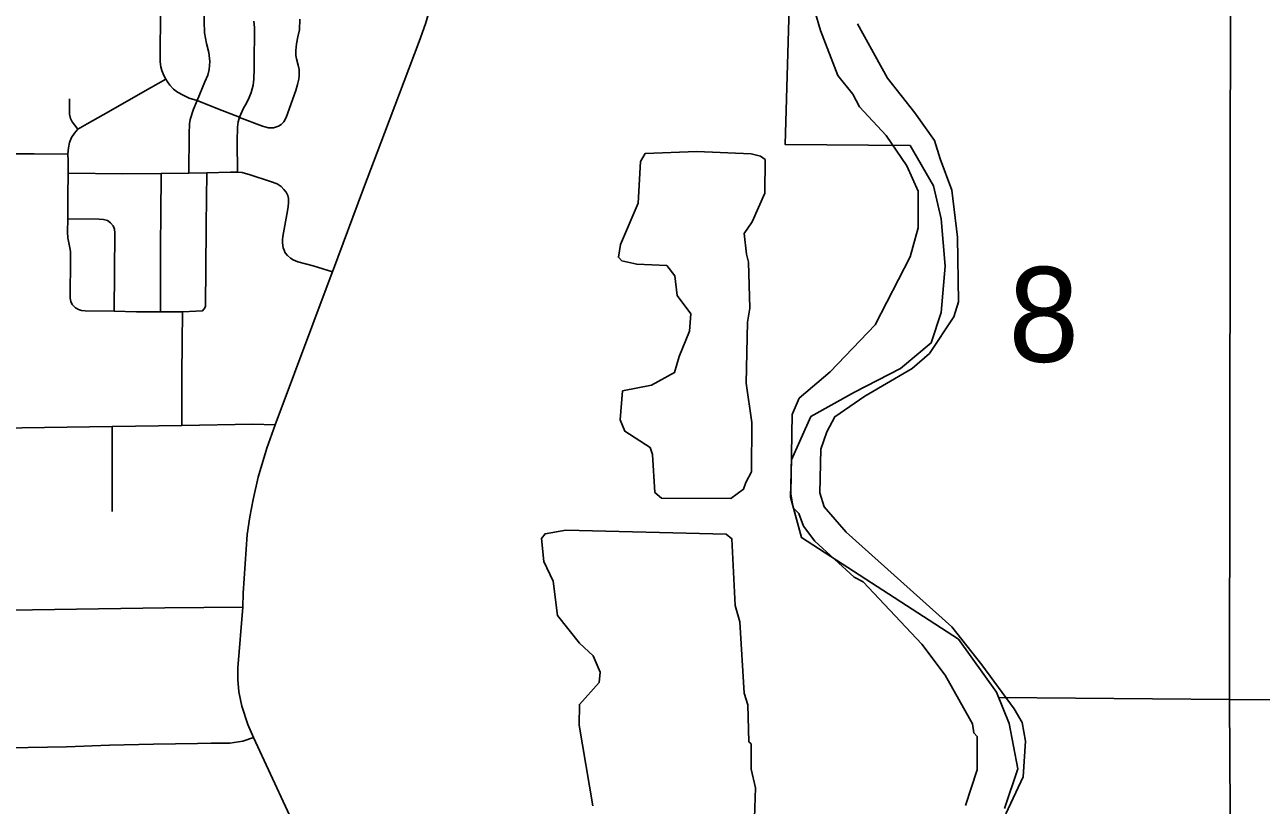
# Model space of a CAD drawing. Extents: x -1403959 to 81668, y -1400582 to 11018.
# Drawn here: x 6835.6 to 6999.4, y 8704.7 to 8808.1 of the extents above; entities that cross this region are included whole.
import ezdxf

# ---------------------------------------------------------------- set-up
doc = ezdxf.new("R2010")
doc.units = 0
for name, color, linetype in [('tdCiRRCL', 7, 'Continuous'), ('tdCiSectNmbr', 7, 'Continuous'), ('tdCiSectTwpRng', 7, 'Continuous'), ('tdCoCityStreetMajor', 7, 'Continuous'), ('tdCoSectLinePart', 7, 'Continuous'), ('tdCoSurfBitum', 7, 'Continuous')]:
    doc.layers.add(name, color=color, linetype=linetype)

msp = doc.modelspace()

# ---------------------------------------------------------------- linework, layer by layer
at = {"layer": 'tdCiRRCL'}
msp.add_lwpolyline([(6936.92, 8811.88), (6936.35, 8792.18), (6952.9, 8792.06), (6956.01, 8786.73), (6956.99, 8782.37), (6957.52, 8776.1), (6957.02, 8769.93), (6955.67, 8765.92), (6951.62, 8762.52), (6945.52, 8759.39), (6939.77, 8756.17), (6937.17, 8750.45), (6937.04, 8745.49), (6938.51, 8740.14), (6959.32, 8726.66), (6964.34, 8719.67), (6966.03, 8715.52), (6967.15, 8709.51), (6965.39, 8704.23)], dxfattribs=at)
at = {"layer": 'tdCiSectNmbr'}
for points in [[(6883.27, 8793.7), (6887.87, 8805.86), (6888.7, 8808.19), (6889.16, 8809.67), (6889.53, 8811.27), (6889.79, 8813.54), (6889.88, 8816.53)], [(6876.35, 8775.24), (6876.39, 8775.35), (6880.5, 8786.37), (6883.27, 8793.7)], [(6864.52, 8730.9), (6864.52, 8730.91), (6864.58, 8732.76), (6865.12, 8740.53), (6865.48, 8742.89), (6865.88, 8745.2), (6866.55, 8748.12), (6867.72, 8751.98), (6868.82, 8755.05), (6876.35, 8775.24)], [(6863.87, 8722.89), (6864.52, 8730.9)], [(6865.96, 8713.64), (6865.2, 8715.36), (6864.42, 8717.8), (6864, 8719.71), (6863.87, 8721.33), (6863.87, 8722.89)], [(6877.05, 8689.29), (6876.08, 8691.57), (6874.93, 8694.25), (6865.96, 8713.64)]]:
    msp.add_lwpolyline(points, dxfattribs=at)
at = {"layer": 'tdCiSectTwpRng'}
for points in [[(6864.08, 8795.81), (6861.23, 8796.91), (6858.48, 8798.01), (6857.44, 8798.35), (6856.61, 8798.73), (6855.88, 8799.15), (6855.34, 8799.55), (6854.87, 8800.06), (6854.56, 8800.5), (6854.32, 8800.85), (6854.08, 8801.32), (6853.81, 8801.99), (6853.67, 8802.5), (6853.6, 8803.14), (6853.58, 8803.62), (6853.57, 8804.36), (6853.6, 8805.45), (6853.67, 8810.75), (6853.71, 8815.6)], [(6857.39, 8788.4), (6857.42, 8793.6), (6857.45, 8794.93), (6857.57, 8795.52), (6858.02, 8796.87), (6858.48, 8798.01), (6859.52, 8800.52), (6859.9, 8801.4), (6860.06, 8802.13), (6860.14, 8803.19), (6860.03, 8804.38), (6859.72, 8805.58), (6859.46, 8807), (6859.41, 8808.5), (6859.44, 8809.93), (6859.59, 8810.86), (6859.86, 8811.38), (6860.25, 8811.69), (6860.84, 8811.9), (6861.75, 8811.95), (6862.5, 8812.06), (6864.18, 8812.79)], [(6863.82, 8788.54), (6863.77, 8792.65), (6863.81, 8794.49), (6863.93, 8795.21), (6864.08, 8795.81), (6864.64, 8797), (6865.03, 8797.67), (6865.39, 8798.41), (6865.64, 8799.09), (6865.88, 8800.06), (6866, 8800.87), (6866.05, 8802.22), (6866.05, 8803.65), (6866.09, 8806.82), (6866.07, 8807.7), (6865.98, 8808.55)], [(6864.11, 8795.79), (6867.13, 8794.65), (6867.44, 8794.54), (6867.92, 8794.41), (6868.23, 8794.41), (6868.59, 8794.4), (6868.87, 8794.49), (6869.24, 8794.62), (6869.61, 8794.84), (6869.96, 8795.21), (6870.26, 8795.77), (6871.55, 8799.35), (6871.79, 8800.13), (6871.95, 8800.84), (6872, 8801.3), (6872.01, 8801.73), (6871.99, 8802.13), (6871.86, 8802.72), (6871.66, 8803.56), (6871.57, 8803.98), (6871.53, 8804.65), (6871.62, 8805.54), (6871.83, 8806.46), (6872.05, 8807.38), (6872.1, 8808.81)], [(6842.68, 8794.25), (6843.92, 8794.93), (6846.76, 8796.51), (6851.27, 8799.12), (6854.32, 8800.85)], [(6842.39, 8770.55), (6842.14, 8770.79), (6841.94, 8771.02), (6841.75, 8771.39), (6841.66, 8771.85), (6841.7, 8777.15), (6841.69, 8778.02), (6841.64, 8778.52), (6841.46, 8779.38), (6841.35, 8779.82), (6841.33, 8780.59), (6841.35, 8782.34), (6841.37, 8785.36), (6841.4, 8788.39), (6841.38, 8790.06), (6841.37, 8790.93), (6841.43, 8791.77), (6841.58, 8792.46), (6841.85, 8793.11), (6842.23, 8793.71), (6842.68, 8794.25), (6842.22, 8794.81), (6841.91, 8795.19), (6841.71, 8795.64), (6841.58, 8796.22), (6841.56, 8796.97), (6841.58, 8798.26)], [(6864.08, 8795.81), (6864.11, 8795.79)], [(6805.19, 8790.6), (6806.03, 8790.62), (6811.16, 8790.73), (6818.54, 8790.83), (6826.52, 8790.94), (6833.99, 8790.98), (6836.9, 8790.96)], [(6836.9, 8790.96), (6841.35, 8790.93)], [(6841.46, 8788.39), (6848.57, 8788.32), (6853.73, 8788.36), (6857.39, 8788.4), (6859.77, 8788.46), (6862.92, 8788.52), (6863.82, 8788.54), (6864.44, 8788.48), (6865.5, 8788.18), (6868.21, 8787.28), (6869.09, 8786.97), (6869.59, 8786.64), (6869.97, 8786.26), (6870.26, 8785.9), (6870.47, 8785.46), (6870.59, 8785.04), (6870.6, 8784.52), (6870.55, 8783.96), (6870.34, 8782.91), (6869.83, 8780), (6869.79, 8779.57), (6869.8, 8779.16), (6869.89, 8778.52), (6870, 8778.19), (6870.15, 8777.86), (6870.45, 8777.48), (6870.83, 8777.15), (6871.21, 8776.91), (6871.81, 8776.68), (6873.85, 8776.12), (6876.39, 8775.35)], [(6859.36, 8770.37), (6859.41, 8770.43), (6859.6, 8770.75), (6859.6, 8771.32), (6859.62, 8775.43), (6859.68, 8781.58), (6859.77, 8788.46)], [(6853.63, 8770.02), (6853.61, 8774.1), (6853.63, 8778.94), (6853.68, 8782.85), (6853.73, 8788.36)], [(6847.49, 8770.12), (6847.6, 8780.48), (6847.54, 8781), (6847.37, 8781.44), (6847.01, 8781.84), (6846.59, 8782.12), (6846.09, 8782.26), (6845.49, 8782.32), (6841.35, 8782.34)], [(6876.39, 8775.35), (6876.39, 8775.35)], [(6842.44, 8770.5), (6842.39, 8770.55)], [(6842.44, 8770.5), (6842.77, 8770.33), (6843.16, 8770.23), (6843.65, 8770.17), (6847.49, 8770.12), (6850.47, 8770.04), (6853.63, 8770.02), (6856.53, 8770.04), (6856.57, 8770.04), (6858.32, 8770.12), (6859.21, 8770.18), (6859.36, 8770.37)], [(6856.46, 8755), (6856.46, 8761.76), (6856.53, 8770.04)], [(6801.61, 8754.24), (6802.08, 8754.25), (6820.11, 8754.46), (6826.26, 8754.55), (6847.24, 8754.86), (6856.46, 8755), (6865.86, 8755.14), (6868.82, 8755.05)], [(6847.21, 8743.6), (6847.24, 8754.86)], [(6801.54, 8730.02), (6854.22, 8730.83), (6864.52, 8730.91)], [(6861.31, 8712.9), (6862.81, 8712.92), (6864.54, 8713.17), (6865.96, 8713.64)], [(6801.54, 8711.82), (6802.04, 8711.83), (6804.54, 8711.85), (6808.96, 8711.97), (6819.49, 8712.14), (6833.59, 8712.29), (6841.18, 8712.43), (6846.86, 8712.64), (6852.7, 8712.76)], [(6852.7, 8712.76), (6858.51, 8712.87), (6860.34, 8712.89), (6861.31, 8712.9)]]:
    msp.add_lwpolyline(points, dxfattribs=at)
at = {"layer": 'tdCoCityStreetMajor'}
for points in [[(6995.17, 8718.69), (6995.33, 8815.64), (6995.33, 8816.37)], [(6964.6, 8718.95), (6995.17, 8718.69)], [(6995.17, 8718.69), (7016.81, 8718.52)], [(6995.17, 8718.69), (6995.75, 8622.19)]]:
    msp.add_lwpolyline(points, dxfattribs=at)
at = {"layer": 'tdCoSurfBitum'}
for points in [[(6960.23, 8704.64), (6961.77, 8709.37), (6961.77, 8713.8), (6961.32, 8714.26), (6961.17, 8715.48), (6957.52, 8721.9), (6954.47, 8726.03), (6946.7, 8734.29), (6945.48, 8734.9), (6940.29, 8739.65), (6938.77, 8741.64), (6938.16, 8743.32), (6937.4, 8744.08), (6937.1, 8745.91), (6937.27, 8756.45), (6938.19, 8758.58), (6942.32, 8762.09), (6948.29, 8768.33), (6952.89, 8777.33), (6953.97, 8781.14), (6953.98, 8786.03), (6952.46, 8789.39), (6949.72, 8793.37), (6946.21, 8797.19), (6945.3, 8798.87), (6943.32, 8801.32), (6941.04, 8807.28), (6939.52, 8812.47)], [(6965.57, 8703.56), (6967.87, 8708.44), (6968.19, 8713.17), (6967.73, 8715.62), (6966.67, 8717.45), (6962.4, 8723.26), (6958.44, 8728.31), (6944.42, 8740.86), (6941.52, 8744.22), (6940.92, 8746.06), (6941.08, 8751.86), (6941.85, 8754.15), (6942.92, 8756.13), (6946.9, 8758.87), (6953.17, 8762.52), (6955.46, 8764.5), (6958.68, 8769.38), (6959.29, 8771.36), (6959.16, 8779.91), (6958.41, 8786.17), (6956.89, 8790.3), (6956.13, 8792.74), (6953.54, 8796.41), (6949.89, 8801), (6945.93, 8808.19)], [(6919.99, 8745.34), (6919.08, 8746.11), (6918.78, 8751.15), (6918.48, 8752.06), (6915.13, 8754.21), (6914.52, 8755.74), (6914.83, 8759.55), (6918.65, 8760.31), (6921.71, 8761.98), (6922.32, 8764.12), (6923.7, 8767.47), (6923.86, 8769.76), (6922.03, 8772.21), (6921.73, 8774.8), (6920.67, 8776.18), (6916.7, 8776.34), (6914.71, 8776.8), (6914.26, 8777.26), (6914.56, 8778.94), (6916.87, 8784.43), (6917.18, 8789.93), (6917.8, 8791), (6924.67, 8791.29), (6931.85, 8790.96), (6933.07, 8790.66), (6933.68, 8790.2), (6933.67, 8785.77), (6931.98, 8781.96), (6930.91, 8780.43), (6931.21, 8777.68), (6931.51, 8776.61), (6931.65, 8770.51), (6931.34, 8768.68), (6931.17, 8760.58), (6931.93, 8755.39), (6931.91, 8748.83), (6931.15, 8747.45), (6930.84, 8746.54), (6929.16, 8745.32), (6919.99, 8745.34)], [(6910.9, 8704.6), (6909.09, 8715.29), (6909.1, 8718.04), (6911.7, 8720.93), (6911.85, 8722.31), (6910.94, 8724.45), (6909.11, 8726.13), (6906.22, 8729.8), (6905.62, 8734.38), (6904.4, 8736.98), (6904.1, 8740.03), (6904.56, 8740.64), (6907.31, 8741.1), (6928.54, 8740.59), (6929.3, 8739.98), (6929.74, 8731.12), (6930.35, 8728.98), (6930.94, 8719.52), (6931.39, 8717.99), (6931.54, 8713.1), (6931.84, 8712.8), (6931.83, 8709.44), (6932.44, 8706.99), (6932.28, 8703.02)]]:
    msp.add_lwpolyline(points, dxfattribs=at)

# ---------------------------------------------------------------- texts
at = {"layer": 'tdCoSectLinePart'}
msp.add_text('8', height=12.57, rotation=359.9936, dxfattribs=at).set_placement((6965.92, 8763.41))

doc.saveas('drawing.dxf')
